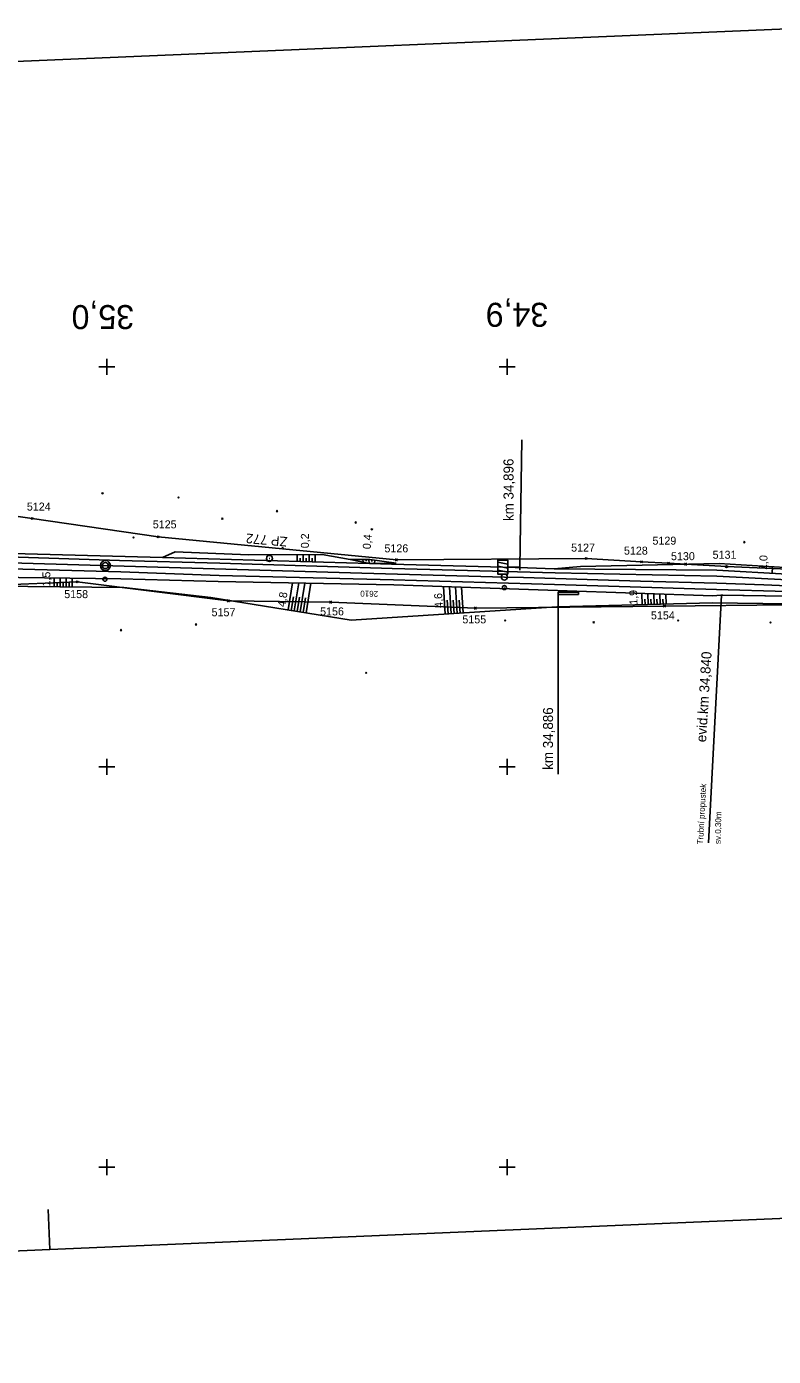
# Model space of a CAD drawing. Extents: x -806456 to -805395, y -1150847 to -1150506.
# Drawn here: x -805820 to -805633.5, y -1150847.3 to -1150515 of the extents above; entities that cross this region are included whole.
import ezdxf

# ---------------------------------------------------------------- set-up
doc = ezdxf.new("R2010")
doc.units = 0
for name, color, linetype in [('0381KM032-037P - Vrstva 1', 7, 'Continuous'), ('0381KM032-037P - Vrstva 19', 7, 'Continuous'), ('0381KM032-037P - Vrstva 4', 7, 'Continuous'), ('0381KM032-037P - Vrstva 48', 7, 'Continuous'), ('0381KM032-037P - Vrstva 49', 7, 'Continuous'), ('0381KM032-037P - Vrstva 57', 7, 'Continuous'), ('0381KM032-037P - Vrstva 7', 7, 'Continuous'), ('0381KM032-037P - Vrstva 9', 7, 'Continuous'), ('formát', 7, 'Continuous'), ('krizky_1000 - Vrstva 1', 7, 'Continuous'), ('szdc - hran DP', 7, 'Continuous'), ('szdc - szdc_cislo', 7, 'Continuous'), ('szdc - szdc_krizek', 7, 'Continuous'), ('vyt_sit - stávající', 7, 'Continuous')]:
    doc.layers.add(name, color=color, linetype=linetype)

msp = doc.modelspace()

# ---------------------------------------------------------------- linework, layer by layer
at = {"layer": '0381KM032-037P - Vrstva 1'}
for points in [[(-805647.61, -1150654.06), (-805666.7, -1150653.55), (-805695.88, -1150652.69), (-805700.7, -1150652.54), (-805736.3, -1150651.55), (-805773.14, -1150650.48), (-805809.82, -1150649.4), (-805847.04, -1150648.36), (-805872.37, -1150647.65)], [(-805607.93, -1150656.05), (-805622.11, -1150655.05), (-805635.9, -1150654.45), (-805647.61, -1150654.06)]]:
    msp.add_lwpolyline(points, dxfattribs=at)
at = {"layer": '0381KM032-037P - Vrstva 19'}
for p, q in [((-805646.42, -1150657.11), (-805649.68, -1150718.98)), ((-805646.66, -1150657.1), (-805646.15, -1150657.11))]:
    msp.add_line(p, q, dxfattribs=at)
for points in [[(-805646.66, -1150657.1), (-805646.66, -1150657.1), (-805646.57, -1150657.13)], [(-805646.27, -1150657.1), (-805646.15, -1150657.11), (-805646.15, -1150657.11)]]:
    msp.add_lwpolyline(points, dxfattribs=at)
msp.add_ellipse((-805646.42, -1150657.11), major_axis=(0.15, 0.019), ratio=0.46044, start_param=6.207328, end_param=9.448235, dxfattribs=at)
at = {"layer": '0381KM032-037P - Vrstva 4'}
msp.add_line((-805728.9, -1150649.35), (-805734.36, -1150649.18), dxfattribs=at)
for points in [[(-805734.36, -1150649.18), (-805786.14, -1150647.68), (-805826.72, -1150646.54), (-805841.05, -1150645.92), (-805859.62, -1150645.3), (-805883.54, -1150644.38), (-805898.84, -1150644.02), (-805920.59, -1150645.08)], [(-805687.98, -1150651.47), (-805728.71, -1150650.4), (-805771.75, -1150649.09), (-805796.82, -1150648.44), (-805827.25, -1150647.42), (-805868.08, -1150645.94), (-805883.57, -1150645.79), (-805899.1, -1150645.56), (-805920.66, -1150646.24), (-805923.83, -1150646.61)], [(-805688.15, -1150654.42), (-805728.36, -1150653.2), (-805771.94, -1150652.19), (-805796.53, -1150651.28), (-805827.23, -1150650.42), (-805883.58, -1150648.86), (-805898.54, -1150648.68), (-805920.02, -1150649.65), (-805923.42, -1150649.97)], [(-805687.42, -1150655.93), (-805728.29, -1150654.47), (-805772.22, -1150653.64), (-805796.51, -1150653.02), (-805828.44, -1150652.6), (-805870.39, -1150650.22), (-805873.51, -1150650.39), (-805883.54, -1150650.55), (-805898.37, -1150650.08), (-805919.92, -1150650.63), (-805923.37, -1150650.9)], [(-805688.26, -1150650.5), (-805694.92, -1150650.2), (-805728.9, -1150649.35)], [(-805485.85, -1150681.76), (-805498.96, -1150678.92), (-805510.6, -1150675.66), (-805525.22, -1150671.48), (-805544.53, -1150665.72), (-805562.31, -1150661.11), (-805574.56, -1150658.15), (-805590.74, -1150655.42), (-805602.22, -1150654.14), (-805617.62, -1150652.74), (-805630.08, -1150651.83), (-805647.65, -1150650.8), (-805688.26, -1150650.5)], [(-805423.97, -1150686.92), (-805425.51, -1150687.49), (-805433.17, -1150688.49), (-805447.58, -1150687.79), (-805460.54, -1150686.52), (-805473.03, -1150684.97), (-805486, -1150682.53), (-805499.06, -1150679.64), (-805510.93, -1150676.58), (-805525.41, -1150672.29), (-805545.14, -1150666.47), (-805562.36, -1150661.85), (-805574.71, -1150659.28), (-805590.7, -1150656.46), (-805602.42, -1150654.96), (-805617.57, -1150653.8), (-805630.08, -1150653.28), (-805647.6, -1150652.35), (-805687.98, -1150651.47)], [(-805425.98, -1150691.47), (-805433.13, -1150691.22), (-805447.47, -1150690.71), (-805460.74, -1150689.57), (-805473.54, -1150687.87), (-805486.2, -1150685.62), (-805499.7, -1150682.42), (-805511.82, -1150679.35), (-805526.11, -1150675.23), (-805545.84, -1150669.48), (-805563.16, -1150664.96), (-805575.57, -1150662.2), (-805590.62, -1150659.46), (-805602.86, -1150658.06), (-805617.64, -1150656.78), (-805630.16, -1150656.16), (-805647.73, -1150655.65), (-805688.15, -1150654.42)], [(-805425.41, -1150692.47), (-805425.98, -1150691.47), (-805433.11, -1150692.35), (-805447.61, -1150691.82), (-805460.9, -1150690.59), (-805473.67, -1150688.98), (-805486.26, -1150686.57), (-805500.08, -1150683.65), (-805512.15, -1150680.12), (-805526.27, -1150676.26), (-805545.98, -1150670.57), (-805563.42, -1150665.87), (-805575.79, -1150663.12), (-805590.93, -1150660.59), (-805603.28, -1150659.09), (-805617.92, -1150657.97), (-805630.11, -1150657.32), (-805646.66, -1150657.1), (-805648.58, -1150657.2), (-805687.42, -1150655.93)]]:
    msp.add_lwpolyline(points, dxfattribs=at)
at = {"layer": '0381KM032-037P - Vrstva 48'}
for p, q in [((-805752.48, -1150648.66), (-805752.44, -1150646.97)), ((-805750.98, -1150648.7), (-805750.94, -1150646.96)), ((-805749.49, -1150648.74), (-805749.43, -1150646.96)), ((-805747.99, -1150648.79), (-805747.93, -1150646.95)), ((-805751.73, -1150648.68), (-805751.71, -1150647.82)), ((-805750.24, -1150648.72), (-805750.21, -1150647.84)), ((-805748.74, -1150648.77), (-805748.71, -1150647.86)), ((-805736.02, -1150648.12), (-805736.01, -1150648.83)), ((-805735.27, -1150648.12), (-805735.26, -1150648.56)), ((-805734.52, -1150648.12), (-805734.51, -1150649.15)), ((-805733.77, -1150648.2), (-805733.84, -1150648.69)), ((-805733.03, -1150648.31), (-805733.15, -1150649.17)), ((-805633.83, -1150651.61), (-805633.73, -1150649.96)), ((-805813.18, -1150654.95), (-805813.15, -1150652.8)), ((-805812.43, -1150654.96), (-805812.41, -1150653.89)), ((-805811.68, -1150654.97), (-805811.65, -1150652.82)), ((-805810.93, -1150654.98), (-805810.91, -1150653.91)), ((-805810.18, -1150654.99), (-805810.15, -1150652.84)), ((-805809.43, -1150654.99), (-805809.41, -1150653.92)), ((-805808.68, -1150655), (-805808.65, -1150652.86)), ((-805754.68, -1150660.78), (-805753.59, -1150653.99)), ((-805753.2, -1150661.01), (-805752.08, -1150654.02)), ((-805751.72, -1150661.25), (-805750.56, -1150654.05)), ((-805750.24, -1150661.49), (-805749.05, -1150654.08)), ((-805715.49, -1150661.81), (-805715.93, -1150654.91)), ((-805713.99, -1150661.71), (-805714.42, -1150654.97)), ((-805712.5, -1150661.62), (-805712.92, -1150655.02)), ((-805711, -1150661.52), (-805711.41, -1150655.07)), ((-805666.28, -1150659.46), (-805666.35, -1150656.62)), ((-805664.78, -1150659.42), (-805664.85, -1150656.67)), ((-805663.28, -1150659.38), (-805663.35, -1150656.72)), ((-805661.78, -1150659.34), (-805661.85, -1150656.77)), ((-805660.28, -1150659.3), (-805660.35, -1150656.81)), ((-805753.94, -1150660.89), (-805753.39, -1150657.45)), ((-805752.46, -1150661.13), (-805751.89, -1150657.58)), ((-805750.98, -1150661.37), (-805750.39, -1150657.72)), ((-805714.74, -1150661.76), (-805714.96, -1150658.35)), ((-805713.24, -1150661.67), (-805713.46, -1150658.33)), ((-805711.75, -1150661.57), (-805711.96, -1150658.31)), ((-805665.53, -1150659.44), (-805665.57, -1150658.04)), ((-805664.03, -1150659.4), (-805664.07, -1150658.04)), ((-805662.53, -1150659.36), (-805662.57, -1150658.05)), ((-805661.03, -1150659.32), (-805661.07, -1150658.05))]:
    msp.add_line(p, q, dxfattribs=at)
at = {"layer": '0381KM032-037P - Vrstva 49'}
for p, q in [((-805801.28, -1150631.44), (-805800.93, -1150631.8)), ((-805801.28, -1150631.8), (-805800.93, -1150631.44)), ((-805782.28, -1150632.48), (-805781.92, -1150632.83)), ((-805782.28, -1150632.83), (-805781.92, -1150632.48)), ((-805757.67, -1150635.89), (-805757.32, -1150636.25)), ((-805757.67, -1150636.25), (-805757.32, -1150635.89)), ((-805770.97, -1150637.78), (-805771.33, -1150638.14)), ((-805771.33, -1150637.78), (-805770.97, -1150638.13)), ((-805738.02, -1150638.73), (-805737.67, -1150639.09)), ((-805738.02, -1150639.09), (-805737.67, -1150638.73)), ((-805733.63, -1150640.45), (-805733.99, -1150640.81)), ((-805733.99, -1150640.45), (-805733.63, -1150640.81)), ((-805793.18, -1150642.5), (-805793.53, -1150642.85)), ((-805793.53, -1150642.5), (-805793.18, -1150642.85)), ((-805640.56, -1150643.67), (-805640.92, -1150644.02)), ((-805640.92, -1150643.67), (-805640.56, -1150644.02)), ((-805700.33, -1150663.23), (-805700.68, -1150663.59)), ((-805700.68, -1150663.23), (-805700.33, -1150663.58)), ((-805678.21, -1150663.68), (-805678.56, -1150664.04)), ((-805678.56, -1150663.69), (-805678.21, -1150664.04)), ((-805657.1, -1150663.22), (-805657.46, -1150663.57)), ((-805657.46, -1150663.22), (-805657.1, -1150663.57)), ((-805634.06, -1150663.7), (-805634.41, -1150664.05)), ((-805634.41, -1150663.7), (-805634.05, -1150664.05)), ((-805796.29, -1150665.66), (-805796.64, -1150666.01)), ((-805796.64, -1150665.66), (-805796.29, -1150666.01)), ((-805777.92, -1150664.26), (-805777.56, -1150664.61)), ((-805777.56, -1150664.26), (-805777.91, -1150664.61)), ((-805735.04, -1150676.33), (-805735.39, -1150676.68)), ((-805735.39, -1150676.33), (-805735.04, -1150676.68))]:
    msp.add_line(p, q, dxfattribs=at)
for points in [[(-805786.14, -1150647.68), (-805826.72, -1150646.54), (-805841.05, -1150645.92)], [(-805786.14, -1150647.68), (-805782.97, -1150646.21), (-805764.63, -1150647), (-805746.23, -1150646.95), (-805739.21, -1150648.13), (-805734.36, -1150649.18), (-805727.71, -1150649.08)], [(-805687.42, -1150655.93), (-805728.29, -1150654.47), (-805772.22, -1150653.64), (-805796.51, -1150653.02), (-805828.44, -1150652.6), (-805870.39, -1150650.22)], [(-805687.58, -1150660.02), (-805738.95, -1150663.31), (-805774.06, -1150657.65), (-805795.8, -1150655.14), (-805835.84, -1150654.7), (-805870.36, -1150656.71), (-805870.39, -1150650.22)], [(-805734.36, -1150649.18), (-805786.14, -1150647.68)], [(-805727.71, -1150649.08), (-805734.34, -1150648.12), (-805739.21, -1150648.13)], [(-805602.19, -1150651.94), (-805630.54, -1150650.16), (-805647.04, -1150649.14), (-805681.66, -1150649.9), (-805688.26, -1150650.5)], [(-805423.97, -1150686.92), (-805433.1, -1150687.91), (-805447.34, -1150686.91), (-805460.49, -1150686.09), (-805485.85, -1150681.76), (-805498.96, -1150678.92), (-805510.6, -1150675.66), (-805525.22, -1150671.48), (-805544.53, -1150665.72), (-805562.31, -1150661.11), (-805571.99, -1150658.79), (-805574.56, -1150658.15), (-805590.74, -1150655.42), (-805602.22, -1150654.14), (-805617.62, -1150652.74), (-805630.08, -1150651.83), (-805647.65, -1150650.8), (-805688.26, -1150650.5)], [(-805425.41, -1150692.47), (-805425.98, -1150691.47), (-805433.11, -1150692.35), (-805447.61, -1150691.82), (-805460.9, -1150690.59), (-805473.67, -1150688.98), (-805486.26, -1150686.57), (-805500.08, -1150683.65), (-805512.15, -1150680.12), (-805526.27, -1150676.26), (-805545.98, -1150670.57), (-805563.42, -1150665.87), (-805575.79, -1150663.12), (-805590.93, -1150660.59), (-805603.28, -1150659.09), (-805617.92, -1150657.97), (-805630.11, -1150657.32), (-805646.15, -1150657.11), (-805646.27, -1150657.1), (-805646.57, -1150657.13), (-805646.66, -1150657.1), (-805648.58, -1150657.2), (-805687.42, -1150655.93)], [(-805428.8, -1150698.61), (-805426.99, -1150695.45), (-805434.79, -1150695.76), (-805452.59, -1150694.8), (-805474.79, -1150691.73), (-805486.9, -1150690.07), (-805513.13, -1150683.83), (-805526.69, -1150679.91), (-805538.18, -1150675.92), (-805547.05, -1150672.92), (-805563.97, -1150668.42), (-805576.87, -1150665.35), (-805586.81, -1150663.24), (-805590.73, -1150662.74), (-805601.92, -1150661.35), (-805629.88, -1150659.22), (-805648.74, -1150658.99), (-805687.58, -1150660.02)]]:
    msp.add_lwpolyline(points, dxfattribs=at)
at = {"layer": '0381KM032-037P - Vrstva 7'}
for p, q in [((-805696.85, -1150650.05), (-805696.3, -1150618.26)), ((-805699.85, -1150649.3), (-805702.35, -1150648.8)), ((-805702.35, -1150649.8), (-805699.85, -1150650.3)), ((-805696.85, -1150650.8), (-805696.85, -1150649.3)), ((-805800.52, -1150653.09), (-805800.42, -1150653.09)), ((-805699.85, -1150651.3), (-805702.35, -1150650.8)), ((-805700.75, -1150655.18), (-805700.65, -1150655.18))]:
    msp.add_line(p, q, dxfattribs=at)
msp.add_lwpolyline([(-805696.85, -1150650.05), (-805699.85, -1150650.05), (-805699.85, -1150648.3), (-805702.35, -1150648.3), (-805702.35, -1150651.8), (-805699.85, -1150651.8), (-805699.85, -1150650.05)], dxfattribs=at)
for centre, radius in [((-805800.37, -1150649.68), 1.25), ((-805800.37, -1150649.68), 0.752), ((-805800.47, -1150653.09), 0.5), ((-805700.7, -1150652.54), 0.75), ((-805700.7, -1150655.18), 0.5)]:
    msp.add_circle(centre, radius, dxfattribs=at)
at = {"layer": '0381KM032-037P - Vrstva 9'}
for p, q in [((-805682.22, -1150656.32), (-805687.22, -1150656.31)), ((-805687.22, -1150656.31), (-805687.22, -1150656.91)), ((-805687.22, -1150656.61), (-805687.22, -1150701.82)), ((-805687.22, -1150656.91), (-805682.22, -1150656.92)), ((-805687.22, -1150656.91), (-805687.22, -1150657.51)), ((-805682.22, -1150656.92), (-805682.22, -1150656.32))]:
    msp.add_line(p, q, dxfattribs=at)
at = {"layer": 'formát'}
for p, q in [((-805617.02, -1150514.97), (-805826.83, -1150523.88)), ((-805814.66, -1150810.62), (-805814.23, -1150820.61)), ((-805604.42, -1150811.7), (-805814.23, -1150820.61)), ((-805814.23, -1150820.61), (-806443.66, -1150847.33))]:
    msp.add_line(p, q, dxfattribs=at)
at = {"layer": 'krizky_1000 - Vrstva 1'}
for points in [[(-805802, -1150600), (-805798, -1150600)], [(-805800, -1150598), (-805800, -1150602)], [(-805702, -1150600), (-805698, -1150600)], [(-805700, -1150598), (-805700, -1150602)], [(-805802, -1150700), (-805798, -1150700)], [(-805800, -1150698), (-805800, -1150702)], [(-805702, -1150700), (-805698, -1150700)], [(-805700, -1150698), (-805700, -1150702)], [(-805802, -1150800), (-805798, -1150800)], [(-805800, -1150798), (-805800, -1150802)], [(-805702, -1150800), (-805698, -1150800)], [(-805700, -1150798), (-805700, -1150802)]]:
    msp.add_lwpolyline(points, dxfattribs=at)
at = {"layer": 'szdc - hran DP'}
for p, q in [((-805827.46, -1150636.65), (-805818.65, -1150637.92)), ((-805818.65, -1150637.92), (-805787.18, -1150642.48)), ((-805787.18, -1150642.48), (-805727.67, -1150648.26)), ((-805727.67, -1150648.26), (-805680.28, -1150647.93)), ((-805680.28, -1150647.93), (-805666.44, -1150648.72)), ((-805666.44, -1150648.72), (-805659.71, -1150649.1)), ((-805659.71, -1150649.1), (-805655.39, -1150649.35)), ((-805655.39, -1150649.35), (-805645.21, -1150649.93)), ((-805645.21, -1150649.93), (-805611.34, -1150651.29)), ((-805807.41, -1150653.77), (-805838.22, -1150654.94)), ((-805769.65, -1150658.51), (-805807.41, -1150653.77)), ((-805744.09, -1150658.84), (-805769.65, -1150658.51)), ((-805707.95, -1150660.33), (-805744.09, -1150658.84)), ((-805660.75, -1150659.79), (-805707.95, -1150660.33)), ((-805629.87, -1150659.45), (-805660.75, -1150659.79))]:
    msp.add_line(p, q, dxfattribs=at)
at = {"layer": 'szdc - szdc_krizek'}
for p, q in [((-805818.39, -1150638.19), (-805818.92, -1150637.66)), ((-805818.92, -1150638.19), (-805818.39, -1150637.66)), ((-805786.92, -1150642.75), (-805787.45, -1150642.22)), ((-805787.45, -1150642.75), (-805786.92, -1150642.22)), ((-805727.41, -1150648.53), (-805727.94, -1150648)), ((-805727.94, -1150648.53), (-805727.41, -1150648)), ((-805680.02, -1150648.2), (-805680.55, -1150647.67)), ((-805680.55, -1150648.2), (-805680.02, -1150647.67)), ((-805666.18, -1150648.99), (-805666.71, -1150648.46)), ((-805666.71, -1150648.99), (-805666.18, -1150648.46)), ((-805659.45, -1150649.36), (-805659.98, -1150648.83)), ((-805659.98, -1150649.36), (-805659.45, -1150648.83)), ((-805655.12, -1150649.61), (-805655.66, -1150649.08)), ((-805655.66, -1150649.61), (-805655.12, -1150649.08)), ((-805644.95, -1150650.2), (-805645.48, -1150649.67)), ((-805645.48, -1150650.2), (-805644.95, -1150649.67)), ((-805807.15, -1150654.03), (-805807.68, -1150653.51)), ((-805807.68, -1150654.03), (-805807.15, -1150653.51)), ((-805769.39, -1150658.78), (-805769.92, -1150658.25)), ((-805769.92, -1150658.78), (-805769.39, -1150658.25)), ((-805743.83, -1150659.1), (-805744.36, -1150658.57)), ((-805744.36, -1150659.1), (-805743.83, -1150658.57)), ((-805707.69, -1150660.59), (-805708.22, -1150660.06)), ((-805708.22, -1150660.59), (-805707.69, -1150660.06)), ((-805660.48, -1150660.05), (-805661.02, -1150659.53)), ((-805661.02, -1150660.05), (-805660.48, -1150659.53))]:
    msp.add_line(p, q, dxfattribs=at)
at = {"layer": 'vyt_sit - stávající'}
msp.add_line((-805759.43, -1150647.88), (-805759.33, -1150647.88), dxfattribs=at)
msp.add_circle((-805759.38, -1150647.88), 0.756, dxfattribs=at)

# ---------------------------------------------------------------- texts
at = {"layer": '0381KM032-037P - Vrstva 19'}
for s, height, rotation, p in [('evid.km 34,840', 2.5, 86.4544, (-805650.31, -1150693.88)), ('Trubní propustek', 1.5, 86.8495, (-805651.08, -1150719.38)), ('sv.0,30m', 1.5, 88.8723, (-805646.65, -1150719.28))]:
    msp.add_text(s, height=height, rotation=rotation, dxfattribs=at).set_placement(p)
at = {"layer": '0381KM032-037P - Vrstva 48'}
for s, rotation, p in [('0,2', 90.1588, (-805749.52, -1150645.34)), ('0,4', 85.1177, (-805734.12, -1150645.65)), ('1,0', 86.4602, (-805635.16, -1150650.83)), ('1,5', 89.3704, (-805814.15, -1150654.92)), ('4,8', 80.8487, (-805755.45, -1150660.12)), ('4,6', 93.6586, (-805716.04, -1150660.2)), ('1,9', 91.5281, (-805667.43, -1150659.46))]:
    msp.add_text(s, height=2, rotation=rotation, dxfattribs=at).set_placement(p)
at = {"layer": '0381KM032-037P - Vrstva 57'}
msp.add_text('2610', height=1.5, rotation=179.2665, dxfattribs=at).set_placement((-805732.22, -1150656.01))
at = {"layer": '0381KM032-037P - Vrstva 7'}
for s, height, rotation, p in [('35,0', 6, 180, (-805793.2, -1150584.57)), ('34,9', 6, 180, (-805689.73, -1150584)), ('km 34,896', 2.5, 90, (-805698.41, -1150638.55))]:
    msp.add_text(s, height=height, rotation=rotation, dxfattribs=at).set_placement(p)
at = {"layer": '0381KM032-037P - Vrstva 9'}
msp.add_text('km 34,886', height=2.5, rotation=89.869, dxfattribs=at).set_placement((-805688.57, -1150700.72))
at = {"layer": 'szdc - szdc_cislo'}
for s, p in [('5124', (-805819.99, -1150635.93)), ('5125', (-805788.53, -1150640.37)), ('5129', (-805663.7, -1150644.45)), ('5126', (-805730.66, -1150646.37)), ('5127', (-805684.02, -1150646.19)), ('5128', (-805670.82, -1150646.94)), ('5130', (-805659.07, -1150648.33)), ('5131', (-805648.67, -1150647.97)), ('5158', (-805810.65, -1150657.81)), ('5157', (-805773.84, -1150662.35)), ('5156', (-805746.73, -1150662.13)), ('5155', (-805711.19, -1150664.12)), ('5154', (-805664.08, -1150663.12))]:
    msp.add_text(s, height=2, dxfattribs=at).set_placement(p)
at = {"layer": 'vyt_sit - stávající'}
msp.add_text('ŽP 772', height=2.4, rotation=175, dxfattribs=at).set_placement((-805754.82, -1150642.56))

doc.saveas('drawing.dxf')
